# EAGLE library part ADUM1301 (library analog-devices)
Triple-Channel Digital Isolators Source: http://www.analog.com/static/imported-files/data_sheets/ADuM1300_1301.pdf
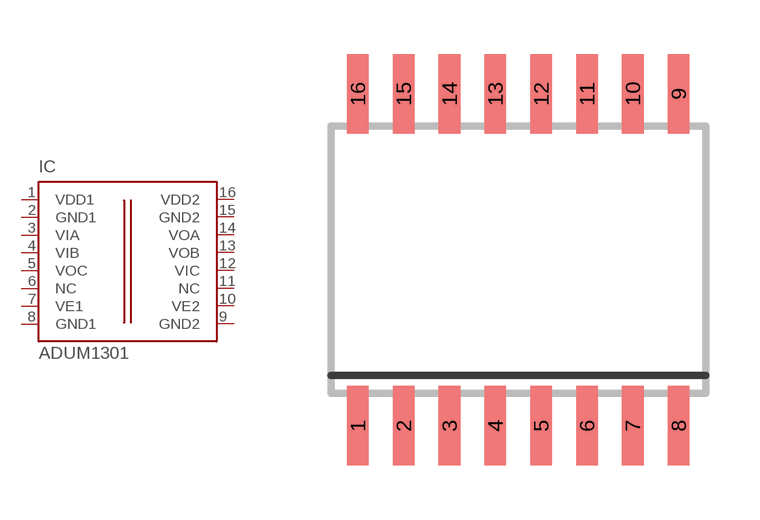
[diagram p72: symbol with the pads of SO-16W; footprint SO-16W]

Designator prefix IC

## ADUM1301 (MPN: ADUM1301BRWZ; OC_FARNELL: 1465623; OC_NEWARK: 19M0757)  [SO-16W]
1  VDD1  in
2  GND1  in
3  VIA  in
4  VIB  in
5  VOC  hiz
6  NC  nc
7  VE1  in
8  GND1  in
9  GND2  in
10  VE2  in
11  NC  nc
12  VIC  in
13  VOB  hiz
14  VOA  hiz
15  GND2  in
16  VDD2  in

## Footprint SO-16W (pad centres in mm)
16-Lead (Wide Body) Small Outline Package (R-16) Source: http://www.analog.com/UploadedFiles/Data_Sheets/409317160AD421_c.pdf
smd 0.6 x 2.2: 1 -4.445,-4.6; 2 -3.175,-4.6; 3 -1.905,-4.6; 4 -0.635,-4.6; 5 0.635,-4.6; 6 1.905,-4.6; 7 3.175,-4.6; 8 4.445,-4.6; 9 4.445,4.6; 10 3.175,4.6; 11 1.905,4.6; 12 0.635,4.6; 13 -0.635,4.6; 14 -1.905,4.6; 15 -3.175,4.6; 16 -4.445,4.6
